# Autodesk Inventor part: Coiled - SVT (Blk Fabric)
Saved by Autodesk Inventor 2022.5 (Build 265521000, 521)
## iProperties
Created: 2024-07
Part Number: Coiled - SVT (Blk Fabric)
Material: Generic
Document SubType Name: Modeling
Designer: AdminForWorker
Density: 1 g/cm^3
Appearance: Default
Title: Coiled - SVT (Blk Fabric)
Author: AdminForWorker
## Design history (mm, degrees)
feature "Coiled - SVT (Blk Fabric)"
body "Solid1"
